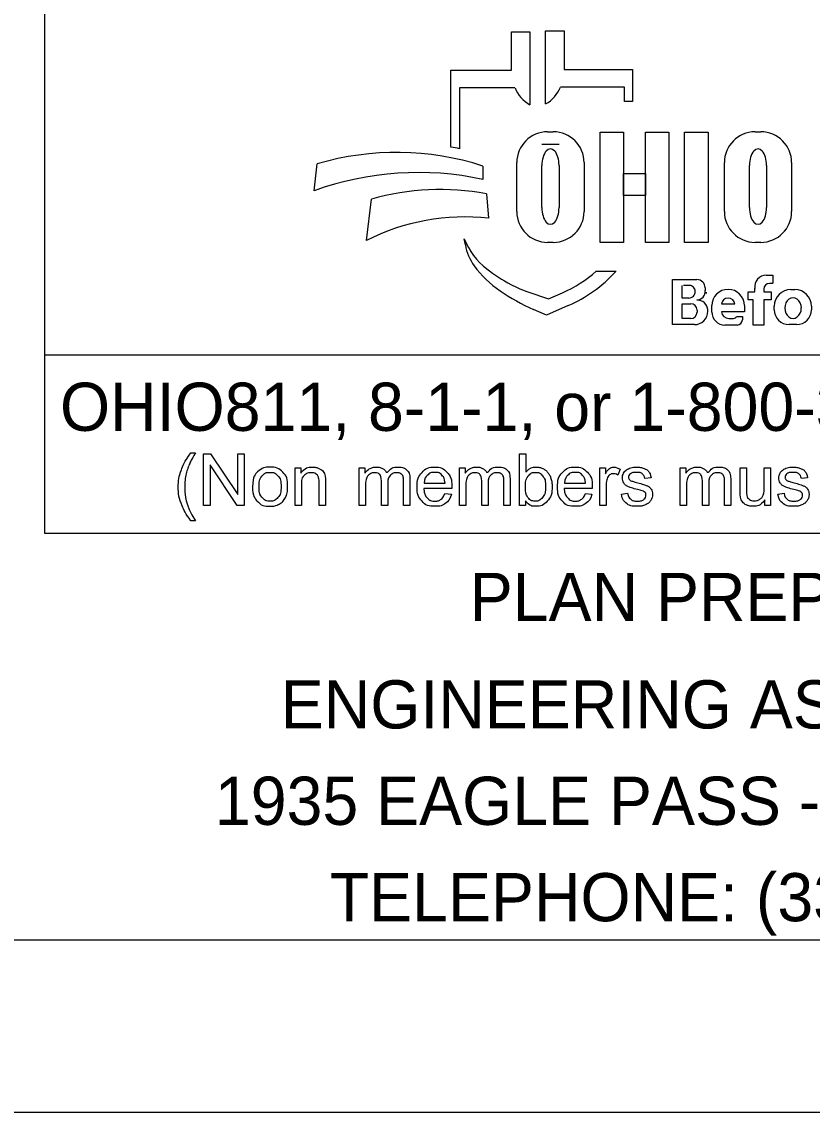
# Model space of a CAD drawing. Extents: x -8.3 to 34, y 0 to 22.
# Drawn here: x 2.311 to 4.607, y 0 to 3.167 of the extents above; entities that cross this region are included whole.
import ezdxf

# ---------------------------------------------------------------- set-up
doc = ezdxf.new("R2010")
doc.units = 0
for name, color, linetype in [('SH_Border', 7, 'Continuous'), ('SH_Cut_Line', 7, 'Continuous'), ('SH_Data', 7, 'Continuous'), ('SH_Text', 7, 'Continuous')]:
    doc.layers.add(name, color=color, linetype=linetype)

msp = doc.modelspace()

# ---------------------------------------------------------------- linework, layer by layer
at = {"layer": 'SH_Border'}
msp.add_lwpolyline([(1.5, 21.5), (33.5, 21.5), (33.5, 0.5), (1.5, 0.5)], close=True, dxfattribs=at)
at = {"layer": 'SH_Cut_Line'}
msp.add_lwpolyline([(0, 0), (34, 0), (34, 22), (0, 22)], close=True, dxfattribs=at)
at = {"layer": 'SH_Data'}
for p, q in [((2.3775, 1.6811), (2.3775, 4.0186)), ((6.6275, 2.199), (2.3775, 2.199)), ((6.6275, 1.6811), (2.3775, 1.6811))]:
    msp.add_line(p, q, dxfattribs=at)
at = {"layer": 'SH_Text'}
for p, q in [((3.7335, 3.0266), (3.7335, 3.1381)), ((3.7335, 3.1381), (3.7872, 3.1381)), ((3.7872, 3.1381), (3.7872, 2.926)), ((3.8329, 2.9284), (3.8329, 3.1404)), ((3.8329, 3.1404), (3.8865, 3.1404)), ((3.8865, 3.1404), (3.8865, 3.029)), ((3.5576, 2.8027), (3.5576, 3.0266)), ((3.5576, 3.0266), (3.7335, 3.0266)), ((3.8865, 3.029), (4.0857, 3.029)), ((4.0857, 3.029), (4.0857, 2.9351)), ((4.0625, 2.9775), (3.8761, 2.9775)), ((4.0625, 2.9351), (4.0625, 2.9775)), ((3.5828, 2.9752), (3.5828, 2.7983)), ((3.7439, 2.9752), (3.5828, 2.9752)), ((4.0857, 2.9351), (4.0625, 2.9351)), ((3.8385, 2.8474), (3.8551, 2.8474)), ((4.4416, 2.8474), (4.4581, 2.8474)), ((3.8718, 2.8104), (3.822, 2.8104)), ((3.7491, 2.616), (3.7491, 2.758)), ((3.9445, 2.758), (3.9445, 2.616)), ((4.3521, 2.616), (4.3521, 2.758)), ((4.5476, 2.758), (4.5476, 2.616)), ((3.1602, 2.6764), (3.1696, 2.7546)), ((3.6509, 2.7481), (3.6509, 2.7092)), ((3.822, 2.6274), (3.822, 2.7497)), ((3.8718, 2.7497), (3.8718, 2.6274)), ((4.425, 2.6274), (4.425, 2.7497)), ((4.4748, 2.7497), (4.4748, 2.6274)), ((3.6608, 2.6675), (3.6671, 2.5965)), ((3.312, 2.5319), (3.3267, 2.652)), ((3.5997, 2.519), (3.5967, 2.5369)), ((3.8551, 2.5265), (3.8385, 2.5265)), ((4.4581, 2.5265), (4.4416, 2.5265)), ((3.98, 2.4431), (4.0375, 2.4431)), ((4.2013, 2.2874), (4.2013, 2.4181)), ((4.2013, 2.4181), (4.2725, 2.4181)), ((4.4739, 2.4309), (4.4934, 2.4309)), ((4.4934, 2.4074), (4.4832, 2.4074)), ((4.4934, 2.4309), (4.4934, 2.4079)), ((3.7816, 2.3827), (3.841, 2.3623)), ((3.841, 2.3623), (3.8821, 2.3801)), ((4.2293, 2.3646), (4.2293, 2.4015)), ((4.2545, 2.4015), (4.2332, 2.4015)), ((4.2963, 2.3943), (4.2963, 2.3864)), ((4.4213, 2.3595), (4.4213, 2.3825)), ((4.4213, 2.3825), (4.4406, 2.3825)), ((4.4406, 2.3825), (4.4406, 2.393)), ((4.4667, 2.3909), (4.4667, 2.3825)), ((4.4667, 2.3825), (4.4883, 2.3825)), ((4.4883, 2.3825), (4.4883, 2.3595)), ((4.5451, 2.3891), (4.5573, 2.3891)), ((4.2487, 2.3646), (4.2293, 2.3646)), ((4.2293, 2.3052), (4.2293, 2.3481)), ((4.2293, 2.3481), (4.2548, 2.3481)), ((4.3824, 2.3465), (4.3439, 2.3465)), ((4.4362, 2.3595), (4.4213, 2.3595)), ((4.4362, 2.2862), (4.4362, 2.3595)), ((4.4883, 2.3595), (4.4667, 2.3595)), ((4.4667, 2.3595), (4.4667, 2.2862)), ((3.835, 2.3152), (3.7976, 2.3317)), ((3.8983, 2.3427), (3.835, 2.3152)), ((4.2729, 2.3299), (4.2729, 2.3236)), ((4.3043, 2.327), (4.3043, 2.3267)), ((4.3159, 2.3241), (4.3159, 2.3426)), ((4.4104, 2.3249), (4.344, 2.3249)), ((4.4104, 2.3426), (4.4104, 2.3249)), ((4.4973, 2.3305), (4.4973, 2.3413)), ((4.6051, 2.3413), (4.6051, 2.3305)), ((4.265, 2.2874), (4.2013, 2.2874)), ((4.2546, 2.3052), (4.2293, 2.3052)), ((4.3892, 2.2862), (4.3538, 2.2862)), ((4.3649, 2.3057), (4.379, 2.3057)), ((4.3876, 2.3112), (4.4045, 2.3112)), ((4.4045, 2.3112), (4.4045, 2.3014)), ((4.4667, 2.2862), (4.4362, 2.2862)), ((4.5623, 2.2877), (4.5401, 2.2877))]:
    msp.add_line(p, q, dxfattribs=at)
for points in [[(3.991, 2.8464), (4.0589, 2.8464), (4.0589, 2.5264), (3.991, 2.5264)], [(4.1231, 2.8464), (4.1911, 2.8464), (4.1911, 2.5264), (4.1231, 2.5264)], [(4.2364, 2.8464), (4.3052, 2.8464), (4.3052, 2.5264), (4.2364, 2.5264)], [(4.0589, 2.7265), (4.1231, 2.7265), (4.1231, 2.6625), (4.0589, 2.6625)]]:
    msp.add_lwpolyline(points, close=True, dxfattribs=at)
for points in [[(2.8021, 1.9149), (2.8153, 1.9149)], [(2.8389, 1.7623), (2.8389, 1.9124), (2.8592, 1.9124), (2.9382, 1.7945), (2.9382, 1.9124), (2.9572, 1.9124), (2.9572, 1.7623), (2.9369, 1.7623), (2.8579, 1.8802), (2.8579, 1.7623), (2.8389, 1.7623)], [(3.7743, 1.7623), (3.7573, 1.7623), (3.7573, 1.9124), (3.7757, 1.9124), (3.7757, 1.8589)], [(3.1048, 1.7623), (3.1048, 1.8711), (3.1214, 1.8711), (3.1214, 1.8556)], [(3.2912, 1.7623), (3.2912, 1.8711), (3.3077, 1.8711), (3.3077, 1.8557)], [(3.5826, 1.7623), (3.5826, 1.8711), (3.5991, 1.8711), (3.5991, 1.8557)], [(3.9904, 1.7623), (3.9904, 1.8711), (4.007, 1.8711), (4.007, 1.8546)], [(4.2236, 1.7623), (4.2236, 1.8711), (4.2401, 1.8711), (4.2401, 1.8557)], [(4.3979, 1.8037), (4.3979, 1.8711), (4.4164, 1.8711), (4.4164, 1.8108)], [(4.4676, 1.8128), (4.4676, 1.8711), (4.4861, 1.8711), (4.4861, 1.7623), (4.4696, 1.7623)], [(3.4388, 1.8369), (3.4388, 1.7623), (3.4203, 1.7623), (3.4203, 1.8307)], [(3.7301, 1.8369), (3.7301, 1.7623), (3.7117, 1.7623), (3.7117, 1.8307)], [(4.0495, 1.8676), (4.043, 1.8505)], [(4.1394, 1.8429), (4.1213, 1.8405)], [(4.3711, 1.8369), (4.3711, 1.7623), (4.3527, 1.7623), (4.3527, 1.8307)], [(4.594, 1.8429), (4.5759, 1.8405)], [(3.1233, 1.8216), (3.1233, 1.7623), (3.1048, 1.7623)], [(3.1932, 1.8291), (3.1932, 1.7623), (3.1748, 1.7623), (3.1748, 1.8284)], [(3.3097, 1.8187), (3.3097, 1.7623), (3.2912, 1.7623)], [(3.3743, 1.8254), (3.3743, 1.7623), (3.3559, 1.7623), (3.3559, 1.8329)], [(3.56, 1.8119), (3.4788, 1.8119)], [(3.4799, 1.827), (3.5406, 1.827)], [(3.601, 1.8187), (3.601, 1.7623), (3.5826, 1.7623)], [(3.6657, 1.8254), (3.6657, 1.7623), (3.6473, 1.7623), (3.6473, 1.8329)], [(3.968, 1.8119), (3.8868, 1.8119)], [(3.8879, 1.827), (3.9486, 1.827)], [(4.0088, 1.8192), (4.0088, 1.7623), (3.9904, 1.7623)], [(4.242, 1.8187), (4.242, 1.7623), (4.2236, 1.7623)], [(4.3067, 1.8254), (4.3067, 1.7623), (4.2883, 1.7623), (4.2883, 1.8329)], [(3.5404, 1.7974), (3.5595, 1.795)], [(3.7743, 1.7759), (3.7743, 1.7623)], [(3.9484, 1.7974), (3.9675, 1.795)], [(4.053, 1.7948), (4.0712, 1.7976)], [(4.4696, 1.7623), (4.4696, 1.7783)], [(4.5076, 1.7948), (4.5258, 1.7976)], [(2.8153, 1.7181), (2.8021, 1.7181)]]:
    msp.add_lwpolyline(points, dxfattribs=at)
for centre, radius, start, end in [((3.7847, 3.0143), 0.0985, 299.2531, 338.0704), ((3.8353, 3.012), 0.0985, 201.9296, 240.7469), ((3.8385, 2.758), 0.0895, 90, 180), ((3.8551, 2.758), 0.0895, 0, 90), ((4.4416, 2.758), 0.0895, 90, 180), ((4.4581, 2.758), 0.0895, 0, 90), ((3.3997, 1.9685), 0.8191, 72.1402, 106.3144), ((3.4295, 1.9938), 0.8191, 79.2074, 81.0007), ((3.4628, 1.8374), 0.8919, 77.8238, 109.8274), ((3.5267, 1.9477), 0.7322, 79.44, 105.8467), ((3.5987, 1.9645), 0.6357, 83.8248, 116.8021), ((3.8385, 2.616), 0.0895, 180, 270), ((3.8551, 2.616), 0.0895, 270, 0), ((4.4416, 2.616), 0.0895, 180, 270), ((4.4581, 2.616), 0.0895, 270, 0), ((3.7841, 2.609), 0.2008, 201.0457, 232.5314), ((3.741, 2.5431), 0.1433, 189.6817, 216.0884), ((3.8747, 2.6405), 0.3088, 216.0884, 235.7167), ((3.9766, 2.8602), 0.5173, 232.5314, 241.794), ((3.7387, 2.7105), 0.3602, 293.4582, 312.0712), ((3.7387, 2.7105), 0.401, 293.4582, 317.8286), ((4.2725, 2.3943), 0.0238, 0, 90), ((4.4739, 2.3973), 0.0335, 90, 187.5187), ((4.4832, 2.3909), 0.0165, 90, 180), ((4.0412, 2.8848), 0.6044, 235.7167, 246.2325), ((3.8914, 2.7014), 0.3371, 241.794, 250.9821), ((4.2487, 2.3833), 0.0187, 270, 2.0582), ((4.2505, 2.3847), 0.0169, 357.8325, 90), ((4.2721, 2.3836), 0.0243, 270, 6.6529), ((4.2827, 2.3821), 0.0175, 347.4023, 0), ((4.3631, 2.3426), 0.0473, 0, 180), ((4.5451, 2.3413), 0.0478, 90, 180), ((4.5573, 2.3413), 0.0478, 0, 90), ((4.2548, 2.3299), 0.0181, 0, 90), ((4.2722, 2.3272), 0.0321, 4.0748, 90), ((4.3632, 2.3455), 0.0193, 2.9632, 177.0368), ((4.2546, 2.3236), 0.0184, 270, 0), ((4.265, 2.3267), 0.0393, 270, 0), ((4.2714, 2.327), 0.033, 0, 11.7502), ((4.3538, 2.3241), 0.038, 180, 270), ((4.3649, 2.3267), 0.021, 184.827, 270), ((4.5401, 2.3305), 0.0428, 180, 270), ((4.5623, 2.3305), 0.0428, 270, 0), ((4.379, 2.315), 0.00938, 270, 335.9979), ((4.3892, 2.3014), 0.0152, 270, 0)]:
    msp.add_arc(centre, radius, start, end, dxfattribs=at)
for centre, major_axis, ratio, start_param, end_param in [((3.8469, 2.7497), (0, 0.0484), 0.514403, 4.712389, 7.853982), ((4.4499, 2.7497), (0, 0.0484), 0.514403, 4.712389, 7.853982), ((3.8469, 2.6274), (0, 0.0484), 0.514403, 1.570796, 4.712389), ((4.4499, 2.6274), (0, 0.0484), 0.514403, 1.570796, 4.712389), ((4.5517, 2.3359), (0, 0.029), 0.832186, 4.712389, 7.853982), ((4.5517, 2.3359), (0, 0.0302), 0.797287, 1.570796, 4.712389)]:
    msp.add_ellipse(centre, major_axis=major_axis, ratio=ratio, start_param=start_param, end_param=end_param, dxfattribs=at)
for points in [[(2.8021, 1.7181), (2.7869, 1.7373), (2.7763, 1.7631), (2.7657, 1.7889), (2.7657, 1.8166), (2.7657, 1.841), (2.7736, 1.8633), (2.7829, 1.8892), (2.8021, 1.9149)], [(2.8153, 1.9149), (2.8029, 1.8936), (2.7989, 1.8845), (2.7927, 1.8704), (2.7891, 1.855), (2.7847, 1.8359), (2.7847, 1.8165), (2.7847, 1.7672), (2.8153, 1.7181)], [(2.9814, 1.8167), (2.9814, 1.8469), (2.9981, 1.8614), (3.0122, 1.8735), (3.0323, 1.8735), (3.0547, 1.8735), (3.069, 1.8588), (3.0832, 1.8441), (3.0832, 1.8182), (3.0832, 1.7972), (3.0769, 1.7852), (3.0706, 1.7732), (3.0586, 1.7665), (3.0466, 1.7598), (3.0323, 1.7598), (3.0095, 1.7598), (2.9954, 1.7745), (2.9814, 1.7891), (2.9814, 1.8167)], [(3.1214, 1.8556), (3.1334, 1.8735), (3.156, 1.8735), (3.1659, 1.8735), (3.1741, 1.87), (3.1823, 1.8664), (3.1864, 1.8607), (3.1905, 1.855), (3.1922, 1.8471), (3.1932, 1.8419), (3.1932, 1.8291)], [(3.3077, 1.8557), (3.3128, 1.8637), (3.3214, 1.8686), (3.3299, 1.8735), (3.3407, 1.8735), (3.3528, 1.8735), (3.3606, 1.8685), (3.3683, 1.8634), (3.3715, 1.8544), (3.3844, 1.8735), (3.4051, 1.8735), (3.4213, 1.8735), (3.43, 1.8645), (3.4388, 1.8556), (3.4388, 1.8369)], [(3.5595, 1.795), (3.555, 1.7783), (3.5428, 1.7691), (3.5306, 1.7598), (3.5117, 1.7598), (3.4878, 1.7598), (3.4738, 1.7745), (3.4598, 1.7892), (3.4598, 1.8157), (3.4598, 1.8432), (3.474, 1.8583), (3.4881, 1.8735), (3.5106, 1.8735), (3.5324, 1.8735), (3.5463, 1.8586), (3.5601, 1.8438), (3.5601, 1.8168), (3.5601, 1.8152), (3.56, 1.8119)], [(3.5991, 1.8557), (3.6042, 1.8637), (3.6127, 1.8686), (3.6212, 1.8735), (3.6321, 1.8735), (3.6442, 1.8735), (3.6519, 1.8685), (3.6597, 1.8634), (3.6628, 1.8544), (3.6758, 1.8735), (3.6965, 1.8735), (3.7127, 1.8735), (3.7214, 1.8645), (3.7301, 1.8556), (3.7301, 1.8369)], [(3.7757, 1.8589), (3.7874, 1.8735), (3.8055, 1.8735), (3.8155, 1.8735), (3.8245, 1.8694), (3.8335, 1.8654), (3.8392, 1.8581), (3.845, 1.8508), (3.8483, 1.8404), (3.8516, 1.8301), (3.8516, 1.8183), (3.8516, 1.7904), (3.8378, 1.7751), (3.8239, 1.7598), (3.8046, 1.7598), (3.7853, 1.7598), (3.7743, 1.7759)], [(3.9675, 1.795), (3.963, 1.7783), (3.9508, 1.7691), (3.9386, 1.7598), (3.9196, 1.7598), (3.8958, 1.7598), (3.8818, 1.7745), (3.8678, 1.7892), (3.8678, 1.8157), (3.8678, 1.8432), (3.882, 1.8583), (3.8961, 1.8735), (3.9186, 1.8735), (3.9404, 1.8735), (3.9543, 1.8586), (3.9681, 1.8438), (3.9681, 1.8168), (3.9681, 1.8152), (3.968, 1.8119)], [(4.007, 1.8546), (4.0133, 1.8661), (4.0187, 1.8698), (4.0241, 1.8735), (4.0305, 1.8735), (4.0398, 1.8735), (4.0495, 1.8676)], [(4.0712, 1.7976), (4.0727, 1.7866), (4.0798, 1.7808), (4.0868, 1.775), (4.0995, 1.775), (4.1122, 1.775), (4.1184, 1.7801), (4.1245, 1.7853), (4.1245, 1.7923), (4.1245, 1.7986), (4.1191, 1.8021), (4.1153, 1.8046), (4.1002, 1.8084), (4.0799, 1.8135), (4.072, 1.8173), (4.0642, 1.821), (4.0601, 1.8276), (4.0561, 1.8342), (4.0561, 1.8422), (4.0561, 1.8494), (4.0594, 1.8556), (4.0628, 1.8618), (4.0685, 1.8659), (4.0728, 1.8691), (4.0803, 1.8713), (4.0877, 1.8735), (4.0962, 1.8735), (4.109, 1.8735), (4.1187, 1.8698), (4.1284, 1.8661), (4.133, 1.8598), (4.1377, 1.8535), (4.1394, 1.8429)], [(4.2401, 1.8557), (4.2452, 1.8637), (4.2537, 1.8686), (4.2622, 1.8735), (4.2731, 1.8735), (4.2852, 1.8735), (4.2929, 1.8685), (4.3007, 1.8634), (4.3038, 1.8544), (4.3168, 1.8735), (4.3375, 1.8735), (4.3537, 1.8735), (4.3624, 1.8645), (4.3711, 1.8556), (4.3711, 1.8369)], [(4.5258, 1.7976), (4.5273, 1.7866), (4.5343, 1.7808), (4.5414, 1.775), (4.554, 1.775), (4.5668, 1.775), (4.5729, 1.7801), (4.5791, 1.7853), (4.5791, 1.7923), (4.5791, 1.7986), (4.5736, 1.8021), (4.5698, 1.8046), (4.5548, 1.8084), (4.5345, 1.8135), (4.5266, 1.8173), (4.5188, 1.821), (4.5147, 1.8276), (4.5107, 1.8342), (4.5107, 1.8422), (4.5107, 1.8494), (4.514, 1.8556), (4.5173, 1.8618), (4.5231, 1.8659), (4.5274, 1.8691), (4.5348, 1.8713), (4.5423, 1.8735), (4.5508, 1.8735), (4.5636, 1.8735), (4.5733, 1.8698), (4.583, 1.8661), (4.5876, 1.8598), (4.5922, 1.8535), (4.594, 1.8429)], [(3.0003, 1.8167), (3.0003, 1.7958), (3.0094, 1.7854), (3.0185, 1.775), (3.0323, 1.775), (3.046, 1.775), (3.0551, 1.7854), (3.0642, 1.7959), (3.0642, 1.8173), (3.0642, 1.8375), (3.0551, 1.8479), (3.0459, 1.8583), (3.0323, 1.8583), (3.0185, 1.8583), (3.0094, 1.8479), (3.0003, 1.8376), (3.0003, 1.8167)], [(3.1748, 1.8284), (3.1748, 1.8397), (3.1726, 1.8452), (3.1705, 1.8508), (3.165, 1.8541), (3.1595, 1.8575), (3.1521, 1.8575), (3.1404, 1.8575), (3.1318, 1.85), (3.1233, 1.8425), (3.1233, 1.8216)], [(3.3559, 1.8329), (3.3559, 1.8452), (3.3514, 1.8513), (3.3469, 1.8575), (3.3366, 1.8575), (3.3288, 1.8575), (3.3222, 1.8534), (3.3156, 1.8493), (3.3126, 1.8414), (3.3097, 1.8335), (3.3097, 1.8187)], [(3.4203, 1.8307), (3.4203, 1.8418), (3.4185, 1.8467), (3.4168, 1.8515), (3.412, 1.8545), (3.4073, 1.8575), (3.401, 1.8575), (3.3895, 1.8575), (3.3819, 1.8498), (3.3743, 1.8422), (3.3743, 1.8254)], [(3.5406, 1.827), (3.5394, 1.8408), (3.5337, 1.8477), (3.5249, 1.8584), (3.5108, 1.8584), (3.4981, 1.8584), (3.4894, 1.8499), (3.4808, 1.8413), (3.4799, 1.827)], [(3.6473, 1.8329), (3.6473, 1.8452), (3.6428, 1.8513), (3.6383, 1.8575), (3.628, 1.8575), (3.6202, 1.8575), (3.6136, 1.8534), (3.607, 1.8493), (3.604, 1.8414), (3.601, 1.8335), (3.601, 1.8187)], [(3.7117, 1.8307), (3.7117, 1.8418), (3.7099, 1.8467), (3.7081, 1.8515), (3.7034, 1.8545), (3.6987, 1.8575), (3.6923, 1.8575), (3.6809, 1.8575), (3.6733, 1.8498), (3.6657, 1.8422), (3.6657, 1.8254)], [(3.7741, 1.8175), (3.7741, 1.7979), (3.7794, 1.7892), (3.7881, 1.775), (3.8029, 1.775), (3.815, 1.775), (3.8238, 1.7855), (3.8326, 1.796), (3.8326, 1.8168), (3.8326, 1.8381), (3.8241, 1.8482), (3.8157, 1.8584), (3.8038, 1.8584), (3.7917, 1.8584), (3.7829, 1.8479), (3.7741, 1.8374), (3.7741, 1.8175)], [(3.9486, 1.827), (3.9474, 1.8408), (3.9417, 1.8477), (3.9328, 1.8584), (3.9188, 1.8584), (3.9061, 1.8584), (3.8974, 1.8499), (3.8888, 1.8413), (3.8879, 1.827)], [(4.043, 1.8505), (4.0363, 1.8545), (4.0295, 1.8545), (4.0235, 1.8545), (4.0187, 1.8509), (4.0139, 1.8472), (4.0119, 1.8408), (4.0088, 1.8309), (4.0088, 1.8192)], [(4.1213, 1.8405), (4.1201, 1.8489), (4.1142, 1.8537), (4.1083, 1.8584), (4.0975, 1.8584), (4.0848, 1.8584), (4.0794, 1.8542), (4.0739, 1.85), (4.0739, 1.8443), (4.0739, 1.8407), (4.0762, 1.8379), (4.0785, 1.8349), (4.0833, 1.8329), (4.086, 1.8319), (4.0996, 1.8282), (4.1192, 1.823), (4.1269, 1.8197), (4.1347, 1.8163), (4.1391, 1.81), (4.1435, 1.8037), (4.1435, 1.7942), (4.1435, 1.785), (4.1381, 1.7769), (4.1327, 1.7688), (4.1226, 1.7643), (4.1124, 1.7598), (4.0996, 1.7598), (4.0784, 1.7598), (4.0672, 1.7687), (4.0561, 1.7775), (4.053, 1.7948)], [(4.2883, 1.8329), (4.2883, 1.8452), (4.2838, 1.8513), (4.2793, 1.8575), (4.269, 1.8575), (4.2612, 1.8575), (4.2546, 1.8534), (4.248, 1.8493), (4.245, 1.8414), (4.242, 1.8335), (4.242, 1.8187)], [(4.3527, 1.8307), (4.3527, 1.8418), (4.3509, 1.8467), (4.3491, 1.8515), (4.3444, 1.8545), (4.3397, 1.8575), (4.3333, 1.8575), (4.3219, 1.8575), (4.3143, 1.8498), (4.3067, 1.8422), (4.3067, 1.8254)], [(4.5759, 1.8405), (4.5747, 1.8489), (4.5688, 1.8537), (4.5629, 1.8584), (4.5521, 1.8584), (4.5394, 1.8584), (4.5339, 1.8542), (4.5285, 1.85), (4.5285, 1.8443), (4.5285, 1.8407), (4.5308, 1.8379), (4.533, 1.8349), (4.5378, 1.8329), (4.5406, 1.8319), (4.5542, 1.8282), (4.5737, 1.823), (4.5815, 1.8197), (4.5893, 1.8163), (4.5937, 1.81), (4.5981, 1.8037), (4.5981, 1.7942), (4.5981, 1.785), (4.5927, 1.7769), (4.5873, 1.7688), (4.5772, 1.7643), (4.567, 1.7598), (4.5542, 1.7598), (4.5329, 1.7598), (4.5218, 1.7687), (4.5107, 1.7775), (4.5076, 1.7948)], [(3.4788, 1.8119), (3.4799, 1.794), (3.489, 1.7845), (3.4981, 1.775), (3.5117, 1.775), (3.5219, 1.775), (3.5291, 1.7803), (3.5362, 1.7857), (3.5404, 1.7974)], [(3.8868, 1.8119), (3.8879, 1.794), (3.897, 1.7845), (3.9061, 1.775), (3.9197, 1.775), (3.9299, 1.775), (3.937, 1.7803), (3.9442, 1.7857), (3.9484, 1.7974)], [(4.4164, 1.8108), (4.4164, 1.7963), (4.4175, 1.7913), (4.4192, 1.7841), (4.4249, 1.7799), (4.4305, 1.7758), (4.4388, 1.7758), (4.4471, 1.7758), (4.4543, 1.78), (4.4616, 1.7843), (4.4646, 1.7916), (4.4676, 1.7989), (4.4676, 1.8128)], [(4.4696, 1.7783), (4.4569, 1.7598), (4.4351, 1.7598), (4.4255, 1.7598), (4.4171, 1.7635), (4.4088, 1.7672), (4.4047, 1.7728), (4.4007, 1.7784), (4.3991, 1.7865), (4.3979, 1.7919), (4.3979, 1.8037)]]:
    msp.add_open_spline(points, degree=3, dxfattribs=at)

# ---------------------------------------------------------------- texts
for s, p in [('OHIO811, 8-1-1, or 1-800-362-2764', (2.422, 1.9789)), ('PLAN PREPARED BY:', (3.6125, 1.4265)), ('ENGINEERING ASSOCIATES, INC.', (3.0634, 1.1145)), ('1935 EAGLE PASS - WOOSTER, OHIO', (2.8721, 0.8345)), ('TELEPHONE: (330) 345-6556', (3.2058, 0.5545))]:
    msp.add_text(s, height=0.14, dxfattribs=at).set_placement(p)

doc.saveas('drawing.dxf')
